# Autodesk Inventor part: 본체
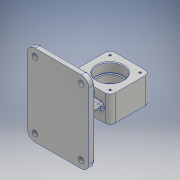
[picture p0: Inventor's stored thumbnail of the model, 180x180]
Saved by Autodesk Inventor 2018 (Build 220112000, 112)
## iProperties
Created: 2020-11
Part Number: 본체
Material: 알루미늄 6061
Document SubType Name: Modeling
Designer: Administrator
Density: 2.7 g/cm^3
Appearance: 알루미늄 - 평지
Mass: 683.214 g
Surface Area: 542.794 cm^2
Volume: 253.042 cm^3
Author: Administrator
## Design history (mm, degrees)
sketch "스케치1"
  geometry: L1 (-32, -32)-(32, -32); L2 (32, -32)-(32, 32); L3 (32, 32)-(-32, 32); L4 (-32, 32)-(-32, -32); L5 (-32, -32)-(32, 32); L6 (32, -32)-(-32, 32); 1 further point
  constraints: 12 end point, 2 midpoint, 2 parallel, 1 horizontal, 1 perpendicular
  dimensions: "d1" = 64 distance of L3.end L2.end; "d2" = 64 distance of L2.end L1.end
extrude "돌출1" new body sketch "스케치1" stored distance "d3" = 42; taper "d4" = 0 deg
sketch "스케치2"
  geometry: L1 (32, 21)-(-32, 21) reference; L2 (0, 21)-(21, 21); L3 (21, 21)-(21, 6); L4 (21, 6)-(0, 6); L5 (0, 6)-(0, 21); L6 (-32, -21)-(32, -21) reference; L7 (0, -21)-(21, -21); L8 (21, -21)-(21, -6); L9 (21, -6)-(0, -6); L10 (0, -6)-(0, -21); L11 (0, 6)-(18, 6); L12 (18, 6)-(18, -6); L13 (18, -6)-(0, -6); L14 (0, -6)-(0, 6); 1 further point
  constraints: 24 end point, 6 parallel, 3 horizontal, 3 perpendicular, 2 midpoint, 1 point on line
  dimensions: "d5" = 21 distance of L3.end L4.end; "d6" = 15 distance of L2.end L3.end; "d7" = 21 distance of L9.end L8.end; "d8" = 15 distance of L8.end L7.end; "d9" = 18 distance of L12.end L13.end
revolve "회전1" sketch "스케치2" stored, may be unused: angle "d10" = 90 deg
sketch "스케치3"
  geometry: L1 (-24, -24)-(24, -24); L2 (24, -24)-(24, 24); L3 (24, 24)-(-24, 24); L4 (-24, 24)-(-24, -24); L5 (-24, -24)-(24, 24); L6 (24, -24)-(-24, 24); 5 further points
  constraints: 12 end point, 4 coincident, 2 midpoint, 2 parallel, 1 horizontal, 1 perpendicular
  dimensions: "d11" = 48 distance of L3.end L2.end; "d12" = 48 distance of L2.end L1.end
hole "구멍1" sketch "스케치3" at (-24, 24), (24, 24), (24, -24), (-24, -24) diameter "d13" = 3.242; stored, may be unused: countersink angle "d17" = 90 deg, drill point angle "d19" = 118 deg; dims "d14" = 8, "d15" = 4, "d16" = 2, "d18" = 10
fillet "모깎기1" dims "d20" = 8
node "작업 평면1"
sketch "스케치4"
  geometry: L1 (0, 0)-(62, 0); L2 (62, 0)-(62, -65); L3 (62, -65)-(-36, -65); L4 (-36, -65)-(-36, 65); L5 (-36, 65)-(62, 65); L6 (62, 65)-(62, 0)
  constraints: 12 end point, 2 perpendicular, 2 vertical, 1 horizontal
  dimensions: "d45" = 62 distance of L1.start L1.end; "d46" = 65 distance of L1.end L2.end; "d47" = 98 distance of L2.end L3.end; "d48" = 130 distance of L3.end L4.end; "d49" = 98 distance of L4.end L5.end
extrude "돌출2" join sketch "스케치4" distance "d50" = 10; taper "d51" = 0 deg
sketch "스케치5"
  geometry: L1 (-4, -17)-(4, -17); L2 (4, -17)-(4, 17); L3 (4, 17)-(-4, 17); L4 (-4, 17)-(-4, -17); L5 (-4, -17)-(4, 17); L6 (4, -17)-(-4, 17); 1 further point
  constraints: 12 end point, 2 midpoint, 2 parallel, 1 horizontal, 1 perpendicular
  dimensions: "d52" = 8 distance of L3.end L2.end; "d53" = 34 distance of L2.end L1.end
extrude "돌출3" join sketch "스케치5" stored distance "d54" = 10; taper "d55" = 0 deg
sketch "스케치6"
  geometry: L1 (-20, -4)-(20, -4); L2 (20, -4)-(20, 4); L3 (20, 4)-(-20, 4); L4 (-20, 4)-(-20, -4); L5 (-20, -4)-(20, 4); L6 (20, -4)-(-20, 4); 1 further point
  constraints: 12 end point, 2 midpoint, 2 parallel, 1 horizontal, 1 perpendicular
  dimensions: "d56" = 40 distance of L3.end L2.end; "d57" = 8 distance of L2.end L1.end
extrude "돌출4" join sketch "스케치6" stored distance "d58" = 10; taper "d59" = 0 deg
sketch "스케치7"
  geometry: C1 r 18 at (0, 0); 1 further point
  constraints: 1 centre point, 1 coincident
  dimensions: "d82" = 36 diameter of C1
extrude "돌출5" cut sketch "스케치7" distance "d60" = 10; taper "d61" = 0 deg
fillet "모깎기2" dims "d62" = 12
sketch "스케치8" dims "d50" = 10, "d51" = 0
  geometry: C1 r 4.5 at (24, -53); C2 r 4.5 at (-50, -53); C3 r 4.5 at (24, 53); C4 r 4.5 at (-50, 53); A1 r 12 centre (24, -53) between (24, -65) and (36, -53) reference; A2 r 12 centre (-50, -53) between (-62, -53) and (-50, -65) reference; A3 r 12 centre (24, 53) between (36, 53) and (24, 65) reference; 1 further point
  constraints: 4 centre point, 3 coincident
  dimensions: "d63" = 9 diameter of C1; "d64" = 9 diameter of C2; "d66" = 9 diameter of C3; "d67" = 9 diameter of C4; "d68" = 86 distance of A3.start C4.centre; "d69" = 136.49908 distance of A1.end C4.centre
extrude "돌출6" cut sketch "스케치8" distance "d70" = 10; taper "d71" = 0 deg
fillet "모깎기3" dims "d72" = 3
fillet "모깎기4" dims "d73" = 3
fillet "모깎기5" dims "d74" = 3
chamfer "모따기1" distance "d75" = 1; stored, may be unused: second distance "d76" = 2, angle "d77" = 45 deg
fillet "모깎기6" dims "d78" = 0.3
sketch "스케치9"
  geometry: L1 (-62, 53)-(-62, -53) reference; L2 (-62, 0)-(-52, 0); 2 further points
  constraints: 2 coincident, 2 end point, 1 horizontal, 1 midpoint, 1 other
  dimensions: "d79" = 10 distance of L2.start L2.end
feature "엠보싱1" sketch "스케치9" dims "d1" = 64, "d2" = 64, "d5" = 21, "d6" = 15, "d7" = 21, "d8" = 15, "d9" = 18, "d80" = 0.5, "d81" = 0
node "솔리드1"
mirror "미러1"
